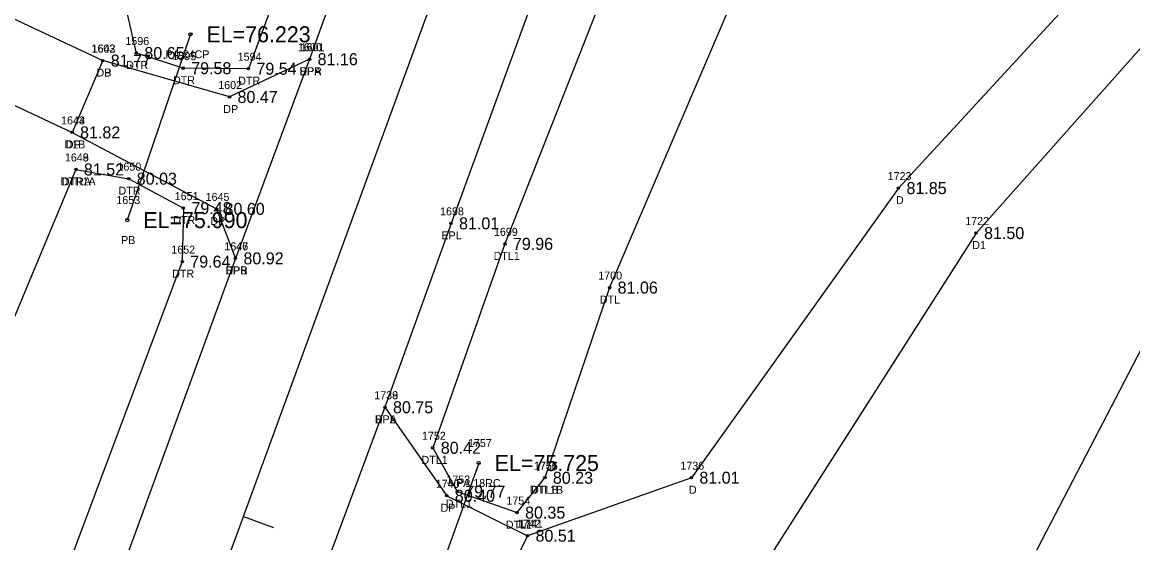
# Model space of a CAD drawing. Extents: x 2139392 to 2143384, y 505395 to 510520.
# Drawn here: x 2141070.2 to 2141208.9, y 509433.7 to 509498.7 of the extents above; entities that cross this region are included whole.
import ezdxf

# ---------------------------------------------------------------- set-up
doc = ezdxf.new("R2010")
doc.units = 0
for name, color, linetype in [('RD_EX_DR_Pipe', 7, 'Continuous'), ('RD_EX_DR_Pipe_txCode', 7, 'Continuous'), ('RD_EX_Driveway', 7, 'Continuous'), ('RD_EX_Driveway_txCode', 7, 'Continuous'), ('RD_EX_Fence_Other', 7, 'Continuous'), ('RD_EX_H2O', 7, 'Continuous'), ('RD_EX_H2O_txCode', 7, 'Continuous'), ('RD_EX_Road', 7, 'Continuous'), ('RD_EX_Road_txCode', 7, 'Continuous'), ('RD_EX_TX_Driveway_ELEV', 7, 'Continuous'), ('RD_EX_TX_H2O_ELEV', 7, 'Continuous'), ('RD_EX_TX_Road_ELEV', 7, 'Continuous'), ('RD_HC_Cl', 7, 'Continuous'), ('RD_HC_Data_Tic', 7, 'Continuous'), ('RD_SMD_Locator', 7, 'Continuous'), ('RD_TX_Pipe_ElevEX', 7, 'Continuous')]:
    doc.layers.add(name, color=color, linetype=linetype)

msp = doc.modelspace()

# ---------------------------------------------------------------- linework, layer by layer
at = {"layer": 'RD_EX_DR_Pipe'}
for p, q in [((2141091.2, 509497.22), (2141083.31, 509474.02)), ((2141127.21, 509443.68), (2141116.83, 509414.76))]:
    msp.add_line(p, q, dxfattribs=at)
at = {"layer": 'RD_EX_Driveway'}
for points in [[(2140954.32, 509598.01), (2140970.97, 509570.04), (2140984.42, 509549.98), (2140986.95, 509546.04), (2140998.62, 509534.73), (2141014.13, 509524.97), (2141080.24, 509493.94)], [(2140947.59, 509589.32), (2140962.02, 509567.84), (2140979.26, 509540.16), (2140995.12, 509524.89), (2141010.76, 509515.89), (2141076.41, 509484.97)], [(2141336.23, 509487.56), (2141285.67, 509513.64), (2141239.88, 509523.87), (2141213.45, 509514.71), (2141179.64, 509478.01), (2141153.77, 509441.85), (2141133.3, 509434.61)], [(2141332.97, 509478.52), (2141281.25, 509505.33), (2141235.66, 509512.77), (2141218.34, 509505.03), (2141189.33, 509472.4), (2141162.86, 509430.93), (2141143.61, 509418.42), (2141126.3, 509420.24)], [(2141106.08, 509494.11), (2141096.08, 509489.39), (2141080.24, 509493.94), (2141076.41, 509484.97), (2141094.46, 509475.41), (2141096.82, 509469.24)], [(2141115.5, 509450.65), (2141123.22, 509439.59), (2141133.3, 509434.61), (2141126.3, 509420.24), (2141117.97, 509422.26), (2141108.98, 509420.55), (2141102.09, 509414.61)]]:
    msp.add_lwpolyline(points, dxfattribs=at)
at = {"layer": 'RD_EX_Fence_Other'}
msp.add_lwpolyline([(2141244.96, 509535.08), (2141227.83, 509492.25), (2141166.83, 509374.98), (2141164.26, 509373.91), (2141120.57, 509389.85)], dxfattribs=at)
at = {"layer": 'RD_EX_H2O'}
for points in [[(2141206.85, 509664.78), (2141205.01, 509659.69), (2141170.77, 509573.35), (2141130.48, 509471.05), (2141121.47, 509445.58), (2141124.52, 509440.12), (2141132, 509437.49), (2141135.47, 509441.84)], [(2141132.18, 509589.57), (2141110.37, 509525.16), (2141098.44, 509492.92), (2141090.29, 509492.99), (2141084.44, 509494.88), (2141082.86, 509501.77)], [(2141183.72, 509559.51), (2141143.56, 509465.59), (2141135.47, 509441.84)], [(2141076.89, 509480.34), (2141038.48, 509388.33), (2141032.76, 509369.34), (2141033.41, 509353.01), (2141044.55, 509348.8)], [(2141076.89, 509480.34), (2141083.49, 509479.19), (2141090.32, 509475.51), (2141090.18, 509468.83), (2141057.26, 509381.22), (2141044.55, 509348.8)]]:
    msp.add_lwpolyline(points, dxfattribs=at)
at = {"layer": 'RD_EX_Road'}
for points in [[(2141389.23, 510293.58), (2141374.66, 510243.58), (2141359.1, 510192.72), (2141341.17, 510140.58), (2141322.74, 510087.97), (2141303.61, 510035.12), (2141287.18, 509990.16), (2141276.99, 509962.02), (2141248.91, 509884.35), (2141213.37, 509787.47), (2141207.76, 509772.94), (2141199.35, 509749.36), (2141191.47, 509727.8), (2141175.93, 509686.04), (2141140.09, 509588.3), (2141106.08, 509494.11), (2141096.82, 509469.24), (2141063.82, 509378.98), (2141052.52, 509348.48), (2141043.48, 509323.88)], [(2141412.62, 510288.46), (2141398.29, 510238.16), (2141381.65, 510185.39), (2141379.05, 510176.51), (2141367.08, 510141.57), (2141363.58, 510131.95), (2141345.23, 510080.36), (2141326.05, 510027.03), (2141308.64, 509979.4), (2141271.24, 509876.37), (2141240, 509789.51), (2141233.78, 509773.43), (2141223.56, 509746.41), (2141212.18, 509714.93), (2141204.36, 509694.36), (2141197.99, 509676.56), (2141193.66, 509664.6), (2141161.61, 509577.24), (2141123.75, 509473.61), (2141115.5, 509450.65), (2141102.09, 509414.61), (2141086.27, 509371.27), (2141050.42, 509272.83)]]:
    msp.add_lwpolyline(points, dxfattribs=at)
at = {"layer": 'RD_HC_Cl'}
msp.add_line((2141333.53, 510081.69), (2140670.51, 508268.37), dxfattribs=at)
at = {"layer": 'RD_HC_Data_Tic'}
msp.add_line((2141097.81, 509437.02), (2141101.57, 509435.64), dxfattribs=at)
at = {"layer": 'RD_SMD_Locator'}
for centre, radius in [((2141091.2, 509497.22), 0.2), ((2141080.24, 509493.94), 0.15), ((2141080.24, 509493.94), 0.15), ((2141084.44, 509494.88), 0.15), ((2141106.08, 509494.11), 0.15), ((2141106.08, 509494.11), 0.15), ((2141090.29, 509492.99), 0.15), ((2141098.44, 509492.92), 0.15), ((2141096.08, 509489.39), 0.15), ((2141076.41, 509484.97), 0.15), ((2141076.41, 509484.97), 0.15), ((2141076.89, 509480.34), 0.15), ((2141076.89, 509480.34), 0.15), ((2141083.49, 509479.19), 0.15), ((2141179.64, 509478.01), 0.15), ((2141090.32, 509475.51), 0.15), ((2141094.46, 509475.41), 0.15), ((2141083.31, 509474.02), 0.2), ((2141123.75, 509473.61), 0.15), ((2141189.33, 509472.4), 0.15), ((2141130.48, 509471.05), 0.15), ((2141090.18, 509468.83), 0.15), ((2141096.82, 509469.24), 0.15), ((2141096.82, 509469.24), 0.15), ((2141143.56, 509465.59), 0.15), ((2141115.5, 509450.65), 0.15), ((2141115.5, 509450.65), 0.15), ((2141121.47, 509445.58), 0.15), ((2141127.21, 509443.68), 0.2), ((2141135.47, 509441.84), 0.15), ((2141135.47, 509441.84), 0.15), ((2141153.77, 509441.85), 0.15), ((2141123.22, 509439.59), 0.15), ((2141124.52, 509440.12), 0.15), ((2141132, 509437.49), 0.15), ((2141133.3, 509434.61), 0.15), ((2141133.3, 509434.61), 0.15)]:
    msp.add_circle(centre, radius, dxfattribs=at)

# ---------------------------------------------------------------- texts
at = {"layer": 'RD_EX_DR_Pipe_txCode'}
for s, p in [('PA 24CP', (2141088.07, 509494.22)), ('1653', (2141081.94, 509476.02)), ('PB', (2141082.53, 509471.02)), ('1757', (2141125.86, 509445.68)), ('PA 18RC', (2141124.37, 509440.68))]:
    msp.add_text(s, height=1, dxfattribs=at).set_placement(p)
at = {"layer": 'RD_EX_Driveway_txCode'}
for s, p in [('1603', (2141078.83, 509494.94)), ('1642', (2141078.87, 509494.94)), ('1601', (2141104.96, 509495.11)), ('DP', (2141079.46, 509491.94)), ('DB', (2141079.46, 509491.94)), ('DPA', (2141104.81, 509492.11)), ('1602', (2141094.67, 509490.39)), ('DP', (2141095.3, 509487.39)), ('1643', (2141075.04, 509485.97)), ('1644', (2141075.04, 509485.97)), ('D1B', (2141075.46, 509482.97)), ('DP', (2141075.63, 509482.97)), ('1723', (2141178.29, 509479.01)), ('1645', (2141093.09, 509476.41)), ('D', (2141179.33, 509476.01)), ('DP', (2141093.68, 509473.41)), ('1722', (2141187.98, 509473.4)), ('1646', (2141095.43, 509470.24)), ('D1', (2141188.86, 509470.4)), ('DPB', (2141095.57, 509467.24)), ('1739', (2141114.16, 509451.65)), ('DPA', (2141114.23, 509448.65)), ('1736', (2141152.4, 509442.85)), ('1740', (2141121.84, 509440.59)), ('D', (2141153.46, 509439.85)), ('DP', (2141122.44, 509437.59)), ('1742', (2141131.96, 509435.61)), ('1741', (2141132.24, 509435.61))]:
    msp.add_text(s, height=1, dxfattribs=at).set_placement(p)
at = {"layer": 'RD_EX_H2O_txCode'}
for s, p in [('1596', (2141083.07, 509495.88)), ('DTR', (2141083.17, 509492.88)), ('1595', (2141088.94, 509493.99)), ('1594', (2141097.1, 509493.92)), ('DTR', (2141089.02, 509490.99)), ('DTR', (2141097.17, 509490.92)), ('1648', (2141075.52, 509481.34)), ('1649', (2141075.52, 509481.34)), ('1650', (2141082.08, 509480.19)), ('DTR1A', (2141074.97, 509478.34)), ('DTRA', (2141075.14, 509478.34)), ('DTR', (2141082.22, 509477.19)), ('1651', (2141089.23, 509476.51)), ('DTR', (2141089.05, 509473.51)), ('1699', (2141129.11, 509472.05)), ('1652', (2141088.81, 509469.83)), ('DTL1', (2141129.07, 509469.05)), ('DTR', (2141088.91, 509466.83)), ('1700', (2141142.14, 509466.59)), ('DTL', (2141142.32, 509463.59)), ('1752', (2141120.12, 509446.58)), ('DTL1', (2141120.06, 509443.58)), ('1756', (2141134.1, 509442.84)), ('1755', (2141134.12, 509442.84)), ('1753', (2141123.17, 509441.12)), ('DTL1B', (2141133.59, 509439.84)), ('DTLB', (2141133.75, 509439.84)), ('DTL1', (2141123.11, 509438.12)), ('1754', (2141130.66, 509438.49)), ('DTL1', (2141130.59, 509435.49))]:
    msp.add_text(s, height=1, dxfattribs=at).set_placement(p)
at = {"layer": 'RD_EX_Road_txCode'}
for s, p in [('1600', (2141104.63, 509495.11)), ('EPR', (2141104.85, 509492.11)), ('1698', (2141122.38, 509474.61)), ('EPL', (2141122.55, 509471.61)), ('1647', (2141095.45, 509470.24)), ('EPR', (2141095.6, 509467.24)), ('1738', (2141114.16, 509451.65)), ('EPL', (2141114.3, 509448.65))]:
    msp.add_text(s, height=1, dxfattribs=at).set_placement(p)
at = {"layer": 'RD_EX_TX_Driveway_ELEV'}
for s, p in [('81.77', (2141081.24, 509493.19)), ('81.77', (2141081.24, 509493.19)), ('81.16', (2141107.08, 509493.36)), ('80.47', (2141097.08, 509488.64)), ('81.82', (2141077.41, 509484.22)), ('81.82', (2141077.41, 509484.22)), ('81.85', (2141180.64, 509477.26)), ('80.60', (2141095.46, 509474.66)), ('81.50', (2141190.33, 509471.65)), ('80.92', (2141097.82, 509468.49)), ('80.75', (2141116.5, 509449.9)), ('81.01', (2141154.77, 509441.1)), ('80.40', (2141124.22, 509438.84)), ('80.51', (2141134.3, 509433.86)), ('80.51', (2141134.3, 509433.86))]:
    msp.add_text(s, height=1.5, dxfattribs=at).set_placement(p)
at = {"layer": 'RD_EX_TX_H2O_ELEV'}
for s, p in [('80.65', (2141085.44, 509494.13)), ('79.58', (2141091.29, 509492.24)), ('79.54', (2141099.44, 509492.17)), ('81.52', (2141077.89, 509479.59)), ('81.52', (2141077.89, 509479.59)), ('80.03', (2141084.49, 509478.44)), ('79.48', (2141091.32, 509474.76)), ('79.96', (2141131.48, 509470.3)), ('79.64', (2141091.18, 509468.08)), ('81.06', (2141144.56, 509464.84)), ('80.42', (2141122.47, 509444.83)), ('80.23', (2141136.47, 509441.09)), ('80.23', (2141136.47, 509441.09)), ('79.77', (2141125.52, 509439.37)), ('80.35', (2141133, 509436.74))]:
    msp.add_text(s, height=1.5, dxfattribs=at).set_placement(p)
at = {"layer": 'RD_EX_TX_Road_ELEV'}
for s, p in [('81.16', (2141107.08, 509493.36)), ('81.01', (2141124.75, 509472.86)), ('80.92', (2141097.82, 509468.49)), ('80.75', (2141116.5, 509449.9))]:
    msp.add_text(s, height=1.5, dxfattribs=at).set_placement(p)
at = {"layer": 'RD_TX_Pipe_ElevEX'}
for s, p in [('EL=76.223', (2141093.2, 509496.22)), ('EL=75.990', (2141085.31, 509473.02)), ('EL=75.725', (2141129.21, 509442.68))]:
    msp.add_text(s, height=2, dxfattribs=at).set_placement(p)

doc.saveas('drawing.dxf')
